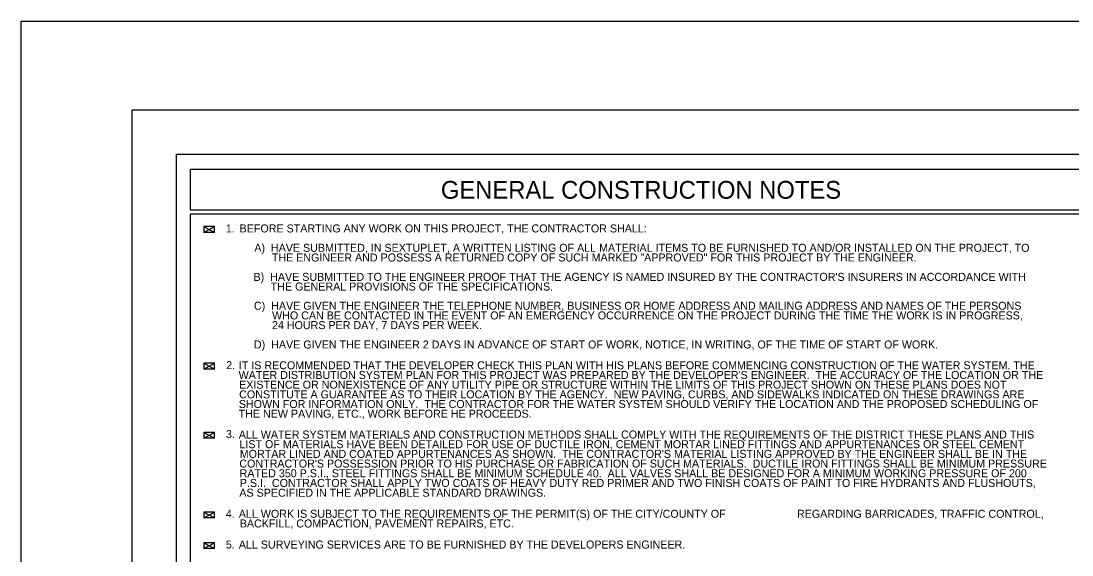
# Model space of a CAD drawing. Extents: x 837 to 1117, y 1316 to 1424.
# Drawn here: x 841.77 to 853.59, y 1416.23 to 1422.24 of the extents above; entities that cross this region are included whole.
import ezdxf

# ---------------------------------------------------------------- set-up
doc = ezdxf.new("R2010")
doc.units = 0
for name, color, linetype in [('0 (Construction)', 7, 'Continuous'), ('BASEMAP', 7, 'Continuous'), ('LLINES', 7, 'Continuous')]:
    doc.layers.add(name, color=color, linetype=linetype)

msp = doc.modelspace()

# ---------------------------------------------------------------- linework, layer by layer
at = {"layer": '0 (Construction)'}
msp.add_lwpolyline([(841.77, 1422.24), (877.77, 1422.24), (877.77, 1398.24), (841.77, 1398.24)], close=True, dxfattribs=at)
at = {"layer": 'BASEMAP'}
for p, q in [((843.02, 1421.24), (877.02, 1421.24)), ((843.02, 1399.24), (843.02, 1421.24)), ((843.52, 1399.74), (843.52, 1420.74)), ((843.52, 1420.74), (876.52, 1420.74)), ((843.678, 1420.113), (843.678, 1420.569)), ((854.857, 1420.569), (843.678, 1420.569)), ((854.857, 1420.113), (843.678, 1420.113)), ((854.857, 1420.065), (843.678, 1420.065)), ((843.678, 1399.867), (843.678, 1420.065))]:
    msp.add_line(p, q, dxfattribs=at)
at = {"layer": 'LLINES'}
for p, q in [((843.828, 1419.861), (843.948, 1419.926)), ((843.828, 1419.926), (843.828, 1419.861)), ((843.828, 1419.926), (843.948, 1419.861)), ((843.948, 1419.926), (843.828, 1419.926)), ((843.948, 1419.861), (843.828, 1419.861)), ((843.948, 1419.861), (843.948, 1419.926)), ((843.948, 1418.388), (843.828, 1418.388)), ((843.828, 1418.388), (843.948, 1418.323)), ((843.828, 1418.388), (843.828, 1418.323)), ((843.828, 1418.323), (843.948, 1418.388)), ((843.948, 1418.323), (843.828, 1418.323)), ((843.948, 1418.323), (843.948, 1418.388)), ((843.828, 1417.546), (843.948, 1417.611)), ((843.828, 1417.611), (843.828, 1417.546)), ((843.828, 1417.611), (843.948, 1417.546)), ((843.948, 1417.611), (843.828, 1417.611)), ((843.948, 1417.546), (843.948, 1417.611)), ((843.948, 1417.546), (843.828, 1417.546)), ((843.948, 1416.715), (843.828, 1416.715)), ((843.828, 1416.715), (843.948, 1416.65)), ((843.828, 1416.715), (843.828, 1416.65)), ((843.828, 1416.65), (843.948, 1416.715)), ((843.948, 1416.65), (843.828, 1416.65)), ((843.948, 1416.65), (843.948, 1416.715)), ((843.828, 1416.304), (843.948, 1416.368)), ((843.828, 1416.368), (843.828, 1416.304)), ((843.828, 1416.368), (843.948, 1416.304)), ((843.948, 1416.368), (843.828, 1416.368)), ((843.948, 1416.304), (843.828, 1416.304)), ((843.948, 1416.304), (843.948, 1416.368))]:
    msp.add_line(p, q, dxfattribs=at)

# ---------------------------------------------------------------- texts
for s, height, p in [('GENERAL CONSTRUCTION NOTES', 0.2, (846.493, 1420.24)), ('1.', 0.09, (844.074, 1419.861)), ('BEFORE STARTING ANY WORK ON THIS PROJECT, THE CONTRACTOR SHALL:', 0.09, (844.229, 1419.861)), ('     A)  HAVE SUBMITTED, IN SEXTUPLET, A WRITTEN LISTING OF ALL MATERIAL ITEMS TO BE FURNISHED TO AND/OR INSTALLED ON THE PROJECT, TO', 0.09, (844.227, 1419.643)), ('         THE ENGINEER AND POSSESS A RETURNED COPY OF SUCH MARKED "APPROVED" FOR THIS PROJECT BY THE ENGINEER.', 0.09, (844.29, 1419.534)), ("     B)  HAVE SUBMITTED TO THE ENGINEER PROOF THAT THE AGENCY IS NAMED INSURED BY THE CONTRACTOR'S INSURERS IN ACCORDANCE WITH", 0.09, (844.218, 1419.316)), ('         THE GENERAL PROVISIONS OF THE SPECIFICATIONS.', 0.09, (844.278, 1419.207)), ('     C)  HAVE GIVEN THE ENGINEER THE TELEPHONE NUMBER, BUSINESS OR HOME ADDRESS AND MAILING ADDRESS AND NAMES OF THE PERSONS', 0.09, (844.223, 1418.991)), ('         WHO CAN BE CONTACTED IN THE EVENT OF AN EMERGENCY OCCURRENCE ON THE PROJECT DURING THE TIME THE WORK IS IN PROGRESS,', 0.09, (844.293, 1418.882)), ('         24 HOURS PER DAY, 7 DAYS PER WEEK.', 0.09, (844.292, 1418.773)), ('     D)  HAVE GIVEN THE ENGINEER 2 DAYS IN ADVANCE OF START OF WORK, NOTICE, IN WRITING, OF THE TIME OF START OF WORK.', 0.09, (844.223, 1418.555)), ('2.', 0.09, (844.078, 1418.323)), ("WATER DISTRIBUTION SYSTEM PLAN FOR THIS PROJECT WAS PREPARED BY THE DEVELOPER'S ENGINEER.  THE ACCURACY OF THE LOCATION OR THE", 0.09, (844.218, 1418.212)), ('IT IS RECOMMENDED THAT THE DEVELOPER CHECK THIS PLAN WITH HIS PLANS BEFORE COMMENCING CONSTRUCTION OF THE WATER SYSTEM. THE', 0.09, (844.22, 1418.321)), ('EXISTENCE OR NONEXISTENCE OF ANY UTILITY PIPE OR STRUCTURE WITHIN THE LIMITS OF THIS PROJECT SHOWN ON THESE PLANS DOES NOT', 0.09, (844.223, 1418.103)), ('CONSTITUTE A GUARANTEE AS TO THEIR LOCATION BY THE AGENCY.  NEW PAVING, CURBS, AND SIDEWALKS INDICATED ON THESE DRAWINGS ARE', 0.09, (844.224, 1417.994)), ('SHOWN FOR INFORMATION ONLY.  THE CONTRACTOR FOR THE WATER SYSTEM SHOULD VERIFY THE LOCATION AND THE PROPOSED SCHEDULING OF', 0.09, (844.22, 1417.885)), ('THE NEW PAVING, ETC., WORK BEFORE HE PROCEEDS.', 0.09, (844.218, 1417.776)), ('3.', 0.09, (844.075, 1417.547)), ('ALL WATER SYSTEM MATERIALS AND CONSTRUCTION METHODS SHALL COMPLY WITH THE REQUIREMENTS OF THE DISTRICT THESE PLANS AND THIS', 0.09, (844.22, 1417.542)), ('LIST OF MATERIALS HAVE BEEN DETAILED FOR USE OF DUCTILE IRON, CEMENT MORTAR LINED FITTINGS AND APPURTENANCES OR STEEL CEMENT', 0.09, (844.227, 1417.433)), ("MORTAR LINED AND COATED APPURTENANCES AS SHOWN.  THE CONTRACTOR'S MATERIAL LISTING APPROVED BY THE ENGINEER SHALL BE IN THE", 0.09, (844.231, 1417.324)), ("CONTRACTOR'S POSSESSION PRIOR TO HIS PURCHASE OR FABRICATION OF SUCH MATERIALS.  DUCTILE IRON FITTINGS SHALL BE MINIMUM PRESSURE", 0.09, (844.226, 1417.215)), ('RATED 350 P.S.I., STEEL FITTINGS SHALL BE MINIMUM SCHEDULE 40.  ALL VALVES SHALL BE DESIGNED FOR A MINIMUM WORKING PRESSURE OF 200', 0.09, (844.229, 1417.106)), ('P.S.I.  CONTRACTOR SHALL APPLY TWO COATS OF HEAVY DUTY RED PRIMER AND TWO FINISH COATS OF PAINT TO FIRE HYDRANTS AND FLUSHOUTS,', 0.09, (844.231, 1416.997)), ('AS SPECIFIED IN THE APPLICABLE STANDARD DRAWINGS.', 0.09, (844.226, 1416.887)), ('4.', 0.09, (844.074, 1416.65)), ('ALL WORK IS SUBJECT TO THE REQUIREMENTS OF THE PERMIT(S) OF THE CITY/COUNTY OF                        REGARDING BARRICADES, TRAFFIC CONTROL,', 0.09, (844.22, 1416.65)), ('BACKFILL, COMPACTION, PAVEMENT REPAIRS, ETC.', 0.09, (844.231, 1416.541)), ('5.', 0.09, (844.074, 1416.304)), ('ALL SURVEYING SERVICES ARE TO BE FURNISHED BY THE DEVELOPERS ENGINEER.', 0.09, (844.22, 1416.304))]:
    msp.add_text(s, height=height, dxfattribs=at).set_placement(p)

doc.saveas('drawing.dxf')
